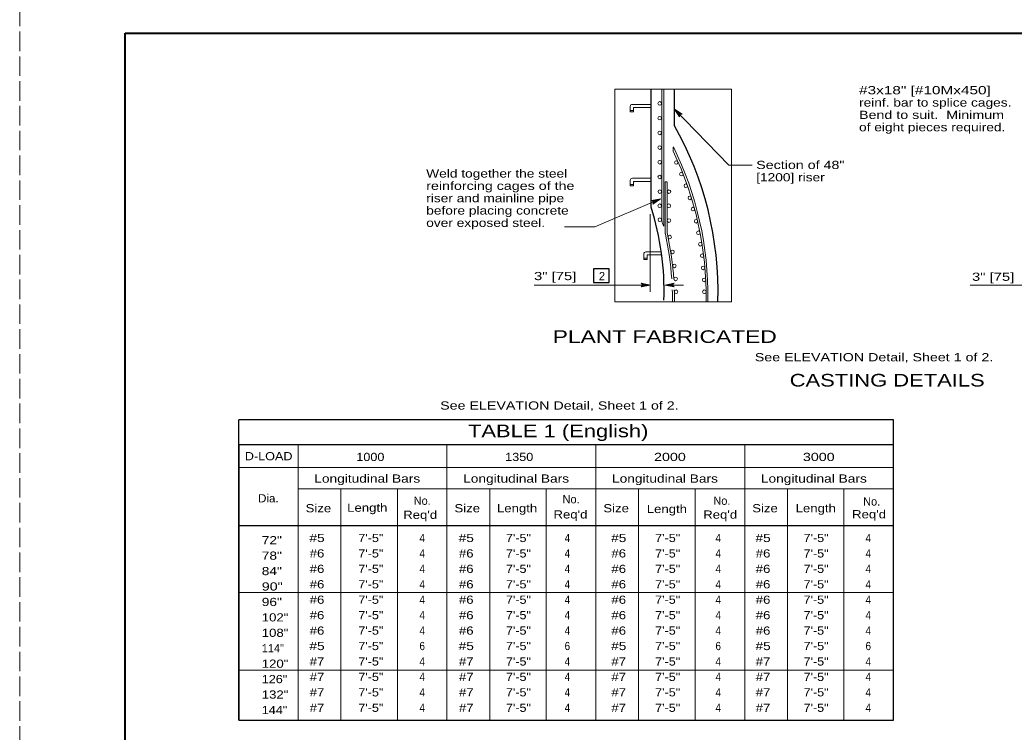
# Model space of a CAD drawing. Extents: x 1170.6 to 1204.6, y 975 to 1019.
# Drawn here: x 1170.59 to 1189.51, y 983.22 to 996.78 of the extents above; entities that cross this region are included whole.
import ezdxf
from ezdxf.enums import TextEntityAlignment as Align

# ---------------------------------------------------------------- set-up
doc = ezdxf.new("R2010")
doc.units = 0
doc.header["$LTSCALE"] = 0.062
doc.linetypes.add('LONG_DASHED', pattern=[7.5, 6, -1.5])
doc.layers.add('1', color=7, linetype='Continuous', lineweight=13)

msp = doc.modelspace()

# ---------------------------------------------------------------- linework, layer by layer
at = {"layer": '1', "lineweight": 25}
for p, q in [((1172.59275, 996.52625), (1204.09275, 996.52625)), ((1182.60175, 993.22908), (1182.60175, 995.45317)), ((1183.03883, 995.45317), (1183.03883, 994.77067)), ((1182.60175, 993.21417), (1182.60175, 993.22908)), ((1187.21383, 989.16408), (1174.75492, 989.16408)), ((1187.21383, 987.12317), (1187.21383, 988.69208)), ((1174.75825, 987.15483), (1187.21383, 987.15483)), ((1174.75492, 983.45158), (1174.75492, 987.12317))]:
    msp.add_line(p, q, dxfattribs=at)
at = {"layer": '1'}
for p, q in [((1182.80342, 992.95783), (1182.80342, 995.45925)), ((1182.84033, 992.85058), (1182.84033, 995.45433)), ((1182.20417, 995.02525), (1182.20417, 995.1305)), ((1182.20417, 995.02525), (1182.20417, 995.1305)), ((1182.60517, 995.16883), (1182.24425, 995.16883)), ((1182.60517, 995.16883), (1182.24425, 995.16883)), ((1182.26833, 995.02525), (1182.26833, 995.09842)), ((1182.26833, 995.02525), (1182.26833, 995.09842)), ((1182.60517, 995.11058), (1182.28058, 995.11058)), ((1182.60517, 995.11058), (1182.28058, 995.11058)), ((1183.15017, 994.97317), (1183.04167, 995.08125)), ((1183.142, 994.96092), (1183.04167, 995.08125)), ((1183.139, 994.94925), (1183.04167, 995.08125)), ((1183.15933, 994.98), (1183.04167, 995.08125)), ((1183.171, 994.984), (1183.04167, 995.08125)), ((1182.20417, 995.04908), (1182.268, 995.04908)), ((1182.20417, 995.04908), (1182.268, 995.04908)), ((1182.20417, 995.02525), (1182.268, 995.02525)), ((1182.20417, 995.02525), (1182.268, 995.02525)), ((1183.0225, 994.27633), (1183.02375, 994.354)), ((1182.60517, 993.76167), (1182.24425, 993.76167)), ((1182.60517, 993.76167), (1182.24425, 993.76167)), ((1182.20417, 993.61808), (1182.20417, 993.72333)), ((1182.20417, 993.61808), (1182.20417, 993.72333)), ((1182.20417, 993.64192), (1182.268, 993.64192)), ((1182.20417, 993.64192), (1182.268, 993.64192)), ((1182.20417, 993.61808), (1182.268, 993.61808)), ((1182.20417, 993.61808), (1182.268, 993.61808)), ((1182.26833, 993.61808), (1182.26833, 993.69117)), ((1182.26833, 993.61808), (1182.26833, 993.69117)), ((1182.60517, 993.70333), (1182.28058, 993.70333)), ((1182.60517, 993.70333), (1182.28058, 993.70333)), ((1182.87067, 993.69475), (1182.8995, 993.69475)), ((1182.87067, 992.70483), (1182.87067, 993.69475)), ((1182.90492, 992.719), (1182.90492, 993.69475)), ((1182.78275, 993.37267), (1181.52933, 992.83692)), ((1182.62608, 993.33225), (1182.78275, 993.37267)), ((1182.63533, 993.324), (1182.78275, 993.37267)), ((1182.64117, 993.31417), (1182.78275, 993.37267)), ((1182.64233, 993.28783), (1182.78275, 993.37267)), ((1182.64408, 993.29983), (1182.78275, 993.37267)), ((1182.58508, 991.60242), (1182.58508, 993.08242)), ((1181.52933, 992.83692), (1180.95542, 992.83692)), ((1182.87367, 992.69725), (1182.87192, 992.70317)), ((1182.91117, 992.69842), (1182.90567, 992.71842)), ((1182.46017, 992.21892), (1182.46017, 992.32417)), ((1182.46017, 992.21892), (1182.46017, 992.32417)), ((1182.46017, 992.24267), (1182.524, 992.24267)), ((1182.46017, 992.24267), (1182.524, 992.24267)), ((1182.78642, 992.3625), (1182.50025, 992.3625)), ((1182.78642, 992.3625), (1182.50025, 992.3625)), ((1182.52433, 992.21892), (1182.52433, 992.292)), ((1182.52433, 992.21892), (1182.52433, 992.292)), ((1182.79525, 992.30417), (1182.53658, 992.30417)), ((1182.79525, 992.30417), (1182.53658, 992.30417)), ((1182.46017, 992.21892), (1182.524, 992.21892)), ((1182.46017, 992.21892), (1182.524, 992.21892)), ((1180.376, 991.73125), (1182.5865, 991.73125)), ((1182.42433, 991.7065), (1182.5865, 991.73125)), ((1182.42625, 991.75367), (1182.5865, 991.73125)), ((1182.4305, 991.71683), (1182.5865, 991.73125)), ((1182.43167, 991.74258), (1182.5865, 991.73125)), ((1182.43333, 991.73125), (1182.5865, 991.73125)), ((1183.0225, 991.75367), (1182.86225, 991.73125)), ((1183.01708, 991.74258), (1182.86225, 991.73125)), ((1182.86225, 991.73125), (1183.21942, 991.73125)), ((1183.01542, 991.73125), (1182.86225, 991.73125)), ((1183.01825, 991.71683), (1182.86225, 991.73125)), ((1183.02442, 991.7065), (1182.86225, 991.73125)), ((1188.66917, 991.72825), (1190.97233, 991.72825)), ((1183.68125, 991.44742), (1183.68125, 991.4075)), ((1187.21383, 988.69208), (1187.21383, 987.12317)), ((1174.75825, 988.25908), (1187.21383, 988.25908)), ((1175.88583, 987.85067), (1187.21383, 987.85067)), ((1174.75825, 985.88175), (1187.21383, 985.88175)), ((1174.75825, 984.40108), (1187.21383, 984.40108))]:
    msp.add_line(p, q, dxfattribs=at)
at = {"layer": '1', "linetype": 'LONG_DASHED'}
msp.add_lwpolyline([(1170.59275, 975.02625), (1204.59275, 975.02625), (1204.59275, 997.02625), (1170.59275, 997.02625)], close=True, dxfattribs=at)
at = {"layer": '1', "lineweight": 25}
for points in [[(1204.09275, 975.52625), (1172.59275, 975.52625), (1172.59275, 996.52625)], [(1174.75492, 987.12317), (1174.75492, 983.45158), (1187.21383, 983.45158), (1187.21383, 989.16408)], [(1187.21383, 988.69208), (1174.75492, 988.69208), (1174.75492, 987.12317), (1174.75492, 989.16408)]]:
    msp.add_lwpolyline(points, dxfattribs=at)
at = {"layer": '1', "lineweight": 40}
msp.add_lwpolyline([(1172.59275, 996.52625), (1204.09275, 996.52625), (1204.09275, 975.52625), (1172.59275, 975.52625)], close=True, dxfattribs=at)
at = {"layer": '1'}
msp.add_lwpolyline([(1181.91333, 995.46083), (1184.12967, 995.46083), (1184.12967, 991.4095), (1181.91333, 991.4095)], close=True, dxfattribs=at)
for points in [[(1183.14208, 994.93125), (1183.04167, 995.08125), (1183.192, 994.98142)], [(1183.04167, 995.08125), (1184.08142, 994.01292), (1184.52358, 994.01292)], [(1182.63267, 993.27242), (1182.78275, 993.37267), (1182.60567, 993.33783)], [(1182.4095, 991.69583), (1182.5865, 991.73125), (1182.4095, 991.76667)], [(1183.03925, 991.69583), (1182.86225, 991.73125), (1183.03925, 991.76667)], [(1175.88583, 988.69208), (1175.88583, 987.12317), (1175.88583, 983.44192)], [(1178.71783, 988.69208), (1178.71783, 987.12317), (1178.71783, 983.44192)], [(1181.54983, 988.69208), (1181.54983, 987.12317), (1181.54983, 983.44192)], [(1184.38183, 988.69208), (1184.38183, 987.12317), (1184.38183, 983.44192)], [(1176.70008, 987.85067), (1176.70008, 987.12317), (1176.70008, 983.44192)], [(1177.77383, 987.85067), (1177.77383, 987.12317), (1177.77383, 983.44192)], [(1179.53208, 987.85067), (1179.53208, 987.12317), (1179.53208, 983.44192)], [(1180.60583, 987.85067), (1180.60583, 987.12317), (1180.60583, 983.44192)], [(1182.36408, 987.85067), (1182.36408, 987.12317), (1182.36408, 983.44192)], [(1183.43783, 987.85067), (1183.43783, 987.12317), (1183.43783, 983.44192)], [(1185.19608, 987.85067), (1185.19608, 987.12317), (1185.19608, 983.44192)], [(1186.26983, 987.85067), (1186.26983, 987.12317), (1186.26983, 983.44192)]]:
    msp.add_lwpolyline(points, dxfattribs=at)
at = {"layer": '1', "lineweight": 25}
msp.add_lwpolyline([(1181.50575, 992.04142), (1181.50575, 991.77967), (1181.80433, 991.77967), (1181.80433, 992.04142)], close=True, dxfattribs=at)
at = {"layer": '1'}
for centre, start, end in [((1183.1772, 994.94625), 67.18798, 203.01411), ((1182.60593, 993.29967), 314.54346, 90.36959), ((1182.39518, 991.73128), 292.08605, 67.91218), ((1183.05357, 991.73128), 112.08782, 247.91395)]:
    msp.add_arc(centre, 0.0382, start, end, dxfattribs=at)
for centre, major_axis, start_param, end_param in [((1182.24522, 995.12507), (0, 0.04383), 0.02303975, 1.4456919), ((1182.24522, 995.12507), (0, 0.04383), 0.02303975, 1.4456919), ((1182.2799, 995.09834), (0, 0.01224), 6.2212346, 7.84973137), ((1182.2799, 995.09834), (0, 0.01224), 6.2212346, 7.84973137), ((1177.92036, 991.53028), (0, 6.09972), 4.69880145, 5.19464595), ((1177.88787, 991.50962), (0, 6.09972), 4.69880145, 5.18317196), ((1182.24522, 993.71788), (0, 0.04383), 0.02303975, 1.4456919), ((1182.24522, 993.71788), (0, 0.04383), 0.02303975, 1.4456919), ((1182.2799, 993.69115), (0, 0.01224), 6.2212346, 7.84973137), ((1182.2799, 993.69115), (0, 0.01224), 6.2212346, 7.84973137), ((1184.87427, 993.65535), (0, -2.30069), 5.02039698, 5.07066013), ((1177.69384, 991.44014), (0, 5.62619), 4.78504801, 4.93773023), ((1177.73128, 991.44131), (0, 5.62619), 4.78241334, 4.93773023), ((1182.50121, 992.31868), (0, 0.04383), 0.02303975, 1.4456919), ((1182.50121, 992.31868), (0, 0.04383), 0.02303975, 1.4456919), ((1182.53588, 992.29195), (0, 0.01224), 6.2212346, 7.84973137), ((1182.53588, 992.29195), (0, 0.01224), 6.2212346, 7.84973137), ((1177.69384, 991.44014), (0, 5.62619), 4.70771426, 4.74802502), ((1177.73128, 991.44131), (0, 5.62619), 4.70771426, 4.74781766)]:
    msp.add_ellipse(centre, major_axis=major_axis, ratio=0.944544, start_param=start_param, end_param=end_param, dxfattribs=at)
for centre in [(1182.76442, 995.18617), (1182.76442, 994.90633), (1182.76442, 994.62649), (1182.76442, 994.34665), (1182.76442, 994.06682), (1183.0794, 994.06248), (1182.76442, 993.78698), (1183.17647, 993.84211), (1183.2597, 993.61932), (1182.7667, 993.5078), (1182.94102, 993.5078), (1183.33601, 993.38912), (1182.76442, 993.23846), (1182.9389, 993.23846), (1183.39611, 993.17608), (1182.76638, 992.97328), (1182.94102, 992.95762), (1183.45621, 992.94596), (1182.95628, 992.64322), (1183.50011, 992.7255), (1183.53708, 992.50755), (1183.00954, 992.36146), (1183.57169, 992.28959), (1183.04423, 992.09445), (1183.59026, 992.05697), (1183.06736, 991.84718), (1183.60874, 991.82919), (1183.07656, 991.60224), (1183.61339, 991.6039)]:
    msp.add_ellipse(centre, major_axis=(0, 0.03466), ratio=0.944544, dxfattribs=at)
at = {"layer": '1', "lineweight": 25}
for centre, major_axis, start_param, end_param in [((1178.11301, 991.60673), (0, 6.09972), 4.68171734, 5.25771769), ((1178.10908, 991.61764), (0, 5.01725), 4.67717352, 5.0362132)]:
    msp.add_ellipse(centre, major_axis=major_axis, ratio=0.944544, start_param=start_param, end_param=end_param, dxfattribs=at)

# ---------------------------------------------------------------- texts
at = {"layer": '1'}
for s, height, width, p in [('#3x18" [#10Mx450]', 0.156, 1.4, (1186.557, 995.36058)), ('reinf. bar to splice cages.', 0.156, 1.25, (1186.557, 995.12592)), ('Bend to suit.  Minimum', 0.156, 1.3, (1186.557, 994.89125)), ('of eight pieces required.', 0.156, 1.25, (1186.557, 994.65658)), ('Section of 48"', 0.156, 1.3, (1184.60025, 993.9385)), ('Weld together the steel', 0.156, 1.25, (1178.32283, 993.77592)), ('[1200] riser', 0.156, 1.25, (1184.60025, 993.70383)), ('reinforcing cages of the', 0.156, 1.3, (1178.32283, 993.54125)), ('riser and mainline pipe', 0.156, 1.25, (1178.32283, 993.30658)), ('before placing concrete', 0.156, 1.25, (1178.32283, 993.07192)), ('over exposed steel.', 0.156, 1.25, (1178.32283, 992.83725)), ('3" [75]', 0.156, 1.35, (1180.37358, 991.82425)), ('3" [75]', 0.156, 1.35, (1188.7055, 991.81125)), ('PLANT FABRICATED ', 0.24, 1.35, (1180.72992, 990.62958)), ('See ELEVATION Detail, Sheet 1 of 2.', 0.156, 1.3, (1184.5735, 990.28008)), ('CASTING DETAILS', 0.24, 1.3, (1185.23758, 989.80025)), ('See ELEVATION Detail, Sheet 1 of 2.', 0.156, 1.3, (1178.58758, 989.361)), ('TABLE 1 (English)', 0.24, 1.3, (1179.11783, 988.83533)), ('D-LOAD', 0.156, 1.15, (1174.87233, 988.39692)), ('1000', 0.156, 1.15, (1176.99317, 988.38275)), ('1350', 0.156, 1.15, (1179.82517, 988.38275)), ('2000', 0.156, 1.3, (1182.65717, 988.38275)), ('3000', 0.156, 1.3, (1185.48917, 988.38275)), ('Longitudinal Bars', 0.156, 1.25, (1176.19358, 987.97083)), ('Longitudinal Bars', 0.156, 1.25, (1179.02558, 987.97083)), ('Longitudinal Bars', 0.156, 1.25, (1181.85758, 987.97083)), ('Longitudinal Bars', 0.156, 1.25, (1184.68958, 987.97083)), ('Dia.', 0.156, 1.05, (1175.125, 987.59542)), ('Size', 0.156, 1.2, (1176.02833, 987.40692)), ('Length', 0.156, 1.2, (1176.81867, 987.41708)), ('Size', 0.156, 1.2, (1178.86033, 987.40692)), ('Length', 0.156, 1.2, (1179.66858, 987.40692)), ('Size', 0.156, 1.2, (1181.69233, 987.40692)), ('Length', 0.156, 1.2, (1182.51842, 987.39233)), ('Size', 0.156, 1.2, (1184.52433, 987.40692)), ('Length', 0.156, 1.2, (1185.35042, 987.40692)), ("Req'd", 0.156, 1.2, (1177.88517, 987.28167)), ("Req'd", 0.156, 1.2, (1180.74375, 987.28875)), ("Req'd", 0.156, 1.2, (1183.59242, 987.28525)), ("Req'd", 0.156, 1.2, (1186.42433, 987.29225)), ('72"', 0.156, 1.25, (1175.19442, 986.79817)), ('78"', 0.156, 1.25, (1175.19442, 986.5045)), ('84"', 0.156, 1.25, (1175.19442, 986.21083)), ('90"', 0.156, 1.3, (1175.19442, 985.91717)), ('96"', 0.156, 1.25, (1175.19442, 985.6235)), ('102"', 0.156, 1.2, (1175.19442, 985.32983)), ('108"', 0.156, 1.2, (1175.19442, 985.03617)), ('120"', 0.156, 1.2, (1175.19442, 984.44883)), ('126"', 0.156, 1.15, (1175.19442, 984.15517)), ('132"', 0.156, 1.2, (1175.19442, 983.8615)), ('144"', 0.156, 1.15, (1175.19442, 983.56783))]:
    msp.add_text(s, height=height, dxfattribs=dict(at, width=width)).set_placement(p)
for s, p in [('2', (1181.60767, 991.82325)), ('No.', (1178.08458, 987.54925)), ('No.', (1180.91675, 987.57742)), ('No.', (1183.78558, 987.54925)), ('No.', (1186.63442, 987.53517)), ('114"', (1175.19442, 984.7425))]:
    msp.add_text(s, height=0.156, dxfattribs=at).set_placement(p)
for s, width, p in [('#5', 1.25, (1176.24554, 986.8405)), ('7\'-5"', 1.15, (1177.26929, 986.8405)), ('4', 0.9, (1178.24662, 986.8405)), ('#5', 1.25, (1179.08446, 986.8405)), ('7\'-5"', 1.15, (1180.07729, 986.8405)), ('4', 0.9, (1181.00804, 986.8405)), ('#5', 1.25, (1181.98554, 986.8405)), ('7\'-5"', 1.15, (1182.91621, 986.8405)), ('4', 0.9, (1183.87804, 986.8405)), ('#5', 1.25, (1184.73138, 986.8405)), ('7\'-5"', 1.15, (1185.73971, 986.8405)), ('4', 0.9, (1186.73254, 986.8405)), ('#6', 1.2, (1176.2455, 986.54683)), ('7\'-5"', 1.15, (1177.26929, 986.54683)), ('4', 0.9, (1178.24662, 986.54683)), ('#6', 1.2, (1179.08442, 986.54683)), ('7\'-5"', 1.15, (1180.07729, 986.54683)), ('4', 0.9, (1181.00804, 986.54683)), ('#6', 1.2, (1181.9855, 986.54683)), ('7\'-5"', 1.15, (1182.91621, 986.54683)), ('4', 0.9, (1183.87804, 986.54683)), ('#6', 1.2, (1184.73133, 986.54683)), ('7\'-5"', 1.15, (1185.73971, 986.54683)), ('4', 0.9, (1186.73254, 986.54683)), ('#6', 1.2, (1176.2455, 986.25317)), ('7\'-5"', 1.15, (1177.26929, 986.25317)), ('4', 0.9, (1178.24662, 986.25317)), ('#6', 1.2, (1179.08442, 986.25317)), ('7\'-5"', 1.15, (1180.07729, 986.25317)), ('4', 0.9, (1181.00804, 986.25317)), ('#6', 1.2, (1181.9855, 986.25317)), ('7\'-5"', 1.15, (1182.91621, 986.25317)), ('4', 0.9, (1183.87804, 986.25317)), ('#6', 1.2, (1184.73133, 986.25317)), ('7\'-5"', 1.15, (1185.73971, 986.25317)), ('4', 0.9, (1186.73254, 986.25317)), ('#6', 1.2, (1176.2455, 985.9595)), ('7\'-5"', 1.15, (1177.26929, 985.9595)), ('4', 0.9, (1178.24662, 985.9595)), ('#6', 1.2, (1179.08442, 985.9595)), ('7\'-5"', 1.15, (1180.07729, 985.9595)), ('4', 0.9, (1181.00804, 985.9595)), ('#6', 1.2, (1181.9855, 985.9595)), ('7\'-5"', 1.15, (1182.91621, 985.9595)), ('4', 0.9, (1183.87804, 985.9595)), ('#6', 1.2, (1184.73133, 985.9595)), ('7\'-5"', 1.15, (1185.73971, 985.9595)), ('4', 0.9, (1186.73254, 985.9595)), ('#6', 1.2, (1176.2455, 985.66583)), ('7\'-5"', 1.15, (1177.26929, 985.66583)), ('4', 0.9, (1178.24662, 985.66583)), ('#6', 1.2, (1179.08442, 985.66583)), ('7\'-5"', 1.15, (1180.07729, 985.66583)), ('4', 0.9, (1181.00804, 985.66583)), ('#6', 1.2, (1181.9855, 985.66583)), ('7\'-5"', 1.15, (1182.91621, 985.66583)), ('4', 0.9, (1183.87804, 985.66583)), ('#6', 1.2, (1184.73133, 985.66583)), ('7\'-5"', 1.15, (1185.73971, 985.66583)), ('4', 0.9, (1186.73254, 985.66583)), ('#6', 1.2, (1176.2455, 985.37217)), ('7\'-5"', 1.15, (1177.26929, 985.37217)), ('4', 0.9, (1178.24662, 985.37217)), ('#6', 1.2, (1179.08442, 985.37217)), ('7\'-5"', 1.15, (1180.07729, 985.37217)), ('4', 0.9, (1181.00804, 985.37217)), ('#6', 1.2, (1181.9855, 985.37217)), ('7\'-5"', 1.15, (1182.91621, 985.37217)), ('4', 0.9, (1183.87804, 985.37217)), ('#6', 1.2, (1184.73133, 985.37217)), ('7\'-5"', 1.15, (1185.73971, 985.37217)), ('4', 0.9, (1186.73254, 985.37217)), ('#6', 1.2, (1176.2455, 985.0785)), ('7\'-5"', 1.15, (1177.26929, 985.0785)), ('4', 0.9, (1178.24662, 985.0785)), ('#6', 1.2, (1179.08442, 985.0785)), ('7\'-5"', 1.15, (1180.07729, 985.0785)), ('4', 0.9, (1181.00804, 985.0785)), ('#6', 1.2, (1181.9855, 985.0785)), ('7\'-5"', 1.15, (1182.91621, 985.0785)), ('4', 0.9, (1183.87804, 985.0785)), ('#6', 1.2, (1184.73133, 985.0785)), ('7\'-5"', 1.15, (1185.73971, 985.0785)), ('4', 0.9, (1186.73254, 985.0785)), ('#5', 1.25, (1176.24554, 984.78483)), ('7\'-5"', 1.15, (1177.26929, 984.78483)), ('6', 0.9, (1178.24662, 984.78483)), ('#5', 1.25, (1179.08446, 984.78483)), ('7\'-5"', 1.15, (1180.07729, 984.78483)), ('6', 0.9, (1181.00804, 984.78483)), ('#5', 1.25, (1181.98554, 984.78483)), ('7\'-5"', 1.15, (1182.91621, 984.78483)), ('6', 0.9, (1183.87804, 984.78483)), ('#5', 1.25, (1184.73138, 984.78483)), ('7\'-5"', 1.15, (1185.73971, 984.78483)), ('6', 0.9, (1186.73254, 984.78483)), ('#7', 1.2, (1176.24554, 984.49117)), ('7\'-5"', 1.15, (1177.26929, 984.49117)), ('4', 0.9, (1178.24662, 984.49117)), ('#7', 1.2, (1179.08446, 984.49117)), ('7\'-5"', 1.15, (1180.07729, 984.49117)), ('4', 0.9, (1181.00804, 984.49117)), ('#7', 1.2, (1181.98554, 984.49117)), ('7\'-5"', 1.15, (1182.91621, 984.49117)), ('4', 0.9, (1183.87804, 984.49117)), ('#7', 1.2, (1184.73138, 984.49117)), ('7\'-5"', 1.15, (1185.73971, 984.49117)), ('4', 0.9, (1186.73254, 984.49117)), ('#7', 1.2, (1176.24554, 984.1975)), ('7\'-5"', 1.15, (1177.26929, 984.1975)), ('4', 0.9, (1178.24662, 984.1975)), ('#7', 1.2, (1179.08446, 984.1975)), ('7\'-5"', 1.15, (1180.07729, 984.1975)), ('4', 0.9, (1181.00804, 984.1975)), ('#7', 1.2, (1181.98554, 984.1975)), ('7\'-5"', 1.15, (1182.91621, 984.1975)), ('4', 0.9, (1183.87804, 984.1975)), ('#7', 1.2, (1184.73138, 984.1975)), ('7\'-5"', 1.15, (1185.73971, 984.1975)), ('4', 0.9, (1186.73254, 984.1975)), ('#7', 1.2, (1176.24554, 983.90383)), ('7\'-5"', 1.15, (1177.26929, 983.90383)), ('4', 0.9, (1178.24662, 983.90383)), ('#7', 1.2, (1179.08446, 983.90383)), ('7\'-5"', 1.15, (1180.07729, 983.90383)), ('4', 0.9, (1181.00804, 983.90383)), ('#7', 1.2, (1181.98554, 983.90383)), ('7\'-5"', 1.15, (1182.91621, 983.90383)), ('4', 0.9, (1183.87804, 983.90383)), ('#7', 1.2, (1184.73138, 983.90383)), ('7\'-5"', 1.15, (1185.73971, 983.90383)), ('4', 0.9, (1186.73254, 983.90383)), ('#7', 1.2, (1176.24554, 983.61017)), ('7\'-5"', 1.15, (1177.26929, 983.61017)), ('4', 0.9, (1178.24662, 983.61017)), ('#7', 1.2, (1179.08446, 983.61017)), ('7\'-5"', 1.15, (1180.07729, 983.61017)), ('4', 0.9, (1181.00804, 983.61017)), ('#7', 1.2, (1181.98554, 983.61017)), ('7\'-5"', 1.15, (1182.91621, 983.61017)), ('4', 0.9, (1183.87804, 983.61017)), ('#7', 1.2, (1184.73138, 983.61017)), ('7\'-5"', 1.15, (1185.73971, 983.61017)), ('4', 0.9, (1186.73254, 983.61017))]:
    msp.add_text(s, height=0.156, dxfattribs=dict(at, width=width)).set_placement(p, align=Align.CENTER)

doc.saveas('drawing.dxf')
